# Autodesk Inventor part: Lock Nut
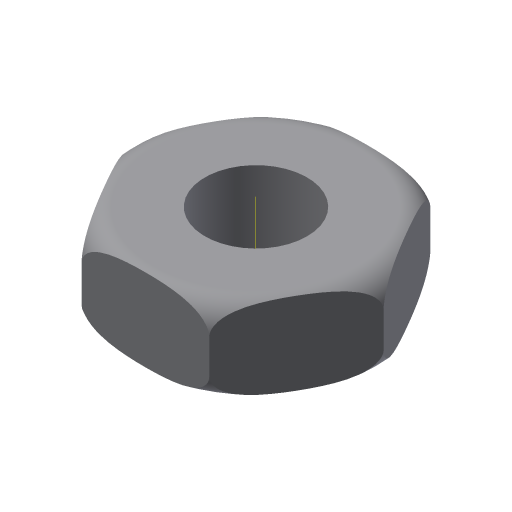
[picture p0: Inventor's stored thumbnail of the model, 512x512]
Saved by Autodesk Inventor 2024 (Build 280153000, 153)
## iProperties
Created: 2009-04
Part Number: Lock Nut
Document SubType Name: Modeling
Designer: Sham
Density: 1 g/cm^3
Material: Generic
Appearance: Default
Mass: 4.65064 g
Surface Area: 21.3319 cm^2
Volume: 4.65064 cm^3
Author: Sham
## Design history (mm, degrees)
sketch "Sketch1"
  geometry: L1 (7.5, 12.99)-(15, 0); L2 (15, 0)-(7.5, -12.99); L3 (7.5, -12.99)-(-7.5, -12.99); L4 (-7.5, -12.99)-(-15, 0); L5 (-15, 0)-(-7.5, 12.99); L6 (-7.5, 12.99)-(7.5, 12.99); C1 r 6 at (0, 0); 1 further point
  constraints: 12 end point, 1 centre point, 1 coincident, 13 other
  dimensions: "d0" = 30 distance of L1.end L4.end; "d1" = 12 diameter of C1
extrude "Extrusion1" new body sketch "Sketch1" distance "d2" = 10; taper "d3" = 0 deg
sketch "Sketch2"
  geometry: L1 (-12, 0)-(-12, -0.022); L2 (-15, 7)-(-15, 3); L3 (0, -2.87)-(0, 12.87) reference; A1 r 3 centre (-12, 7) between (-12, 10) and (-15, 7); A2 r 3 centre (-12, 3) between (-15, 3) and (-12, 0)
  constraints: 4 end point, 4 point on circle, 2 centre point, 1 tangent
revolve "Revolution1" sketch "Sketch2" stored, may be unused: angle "d7" = 90 deg
body "Solid1"
other parameters: "d6" = 90 deg
